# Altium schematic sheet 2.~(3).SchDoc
size 420 x 297 mm
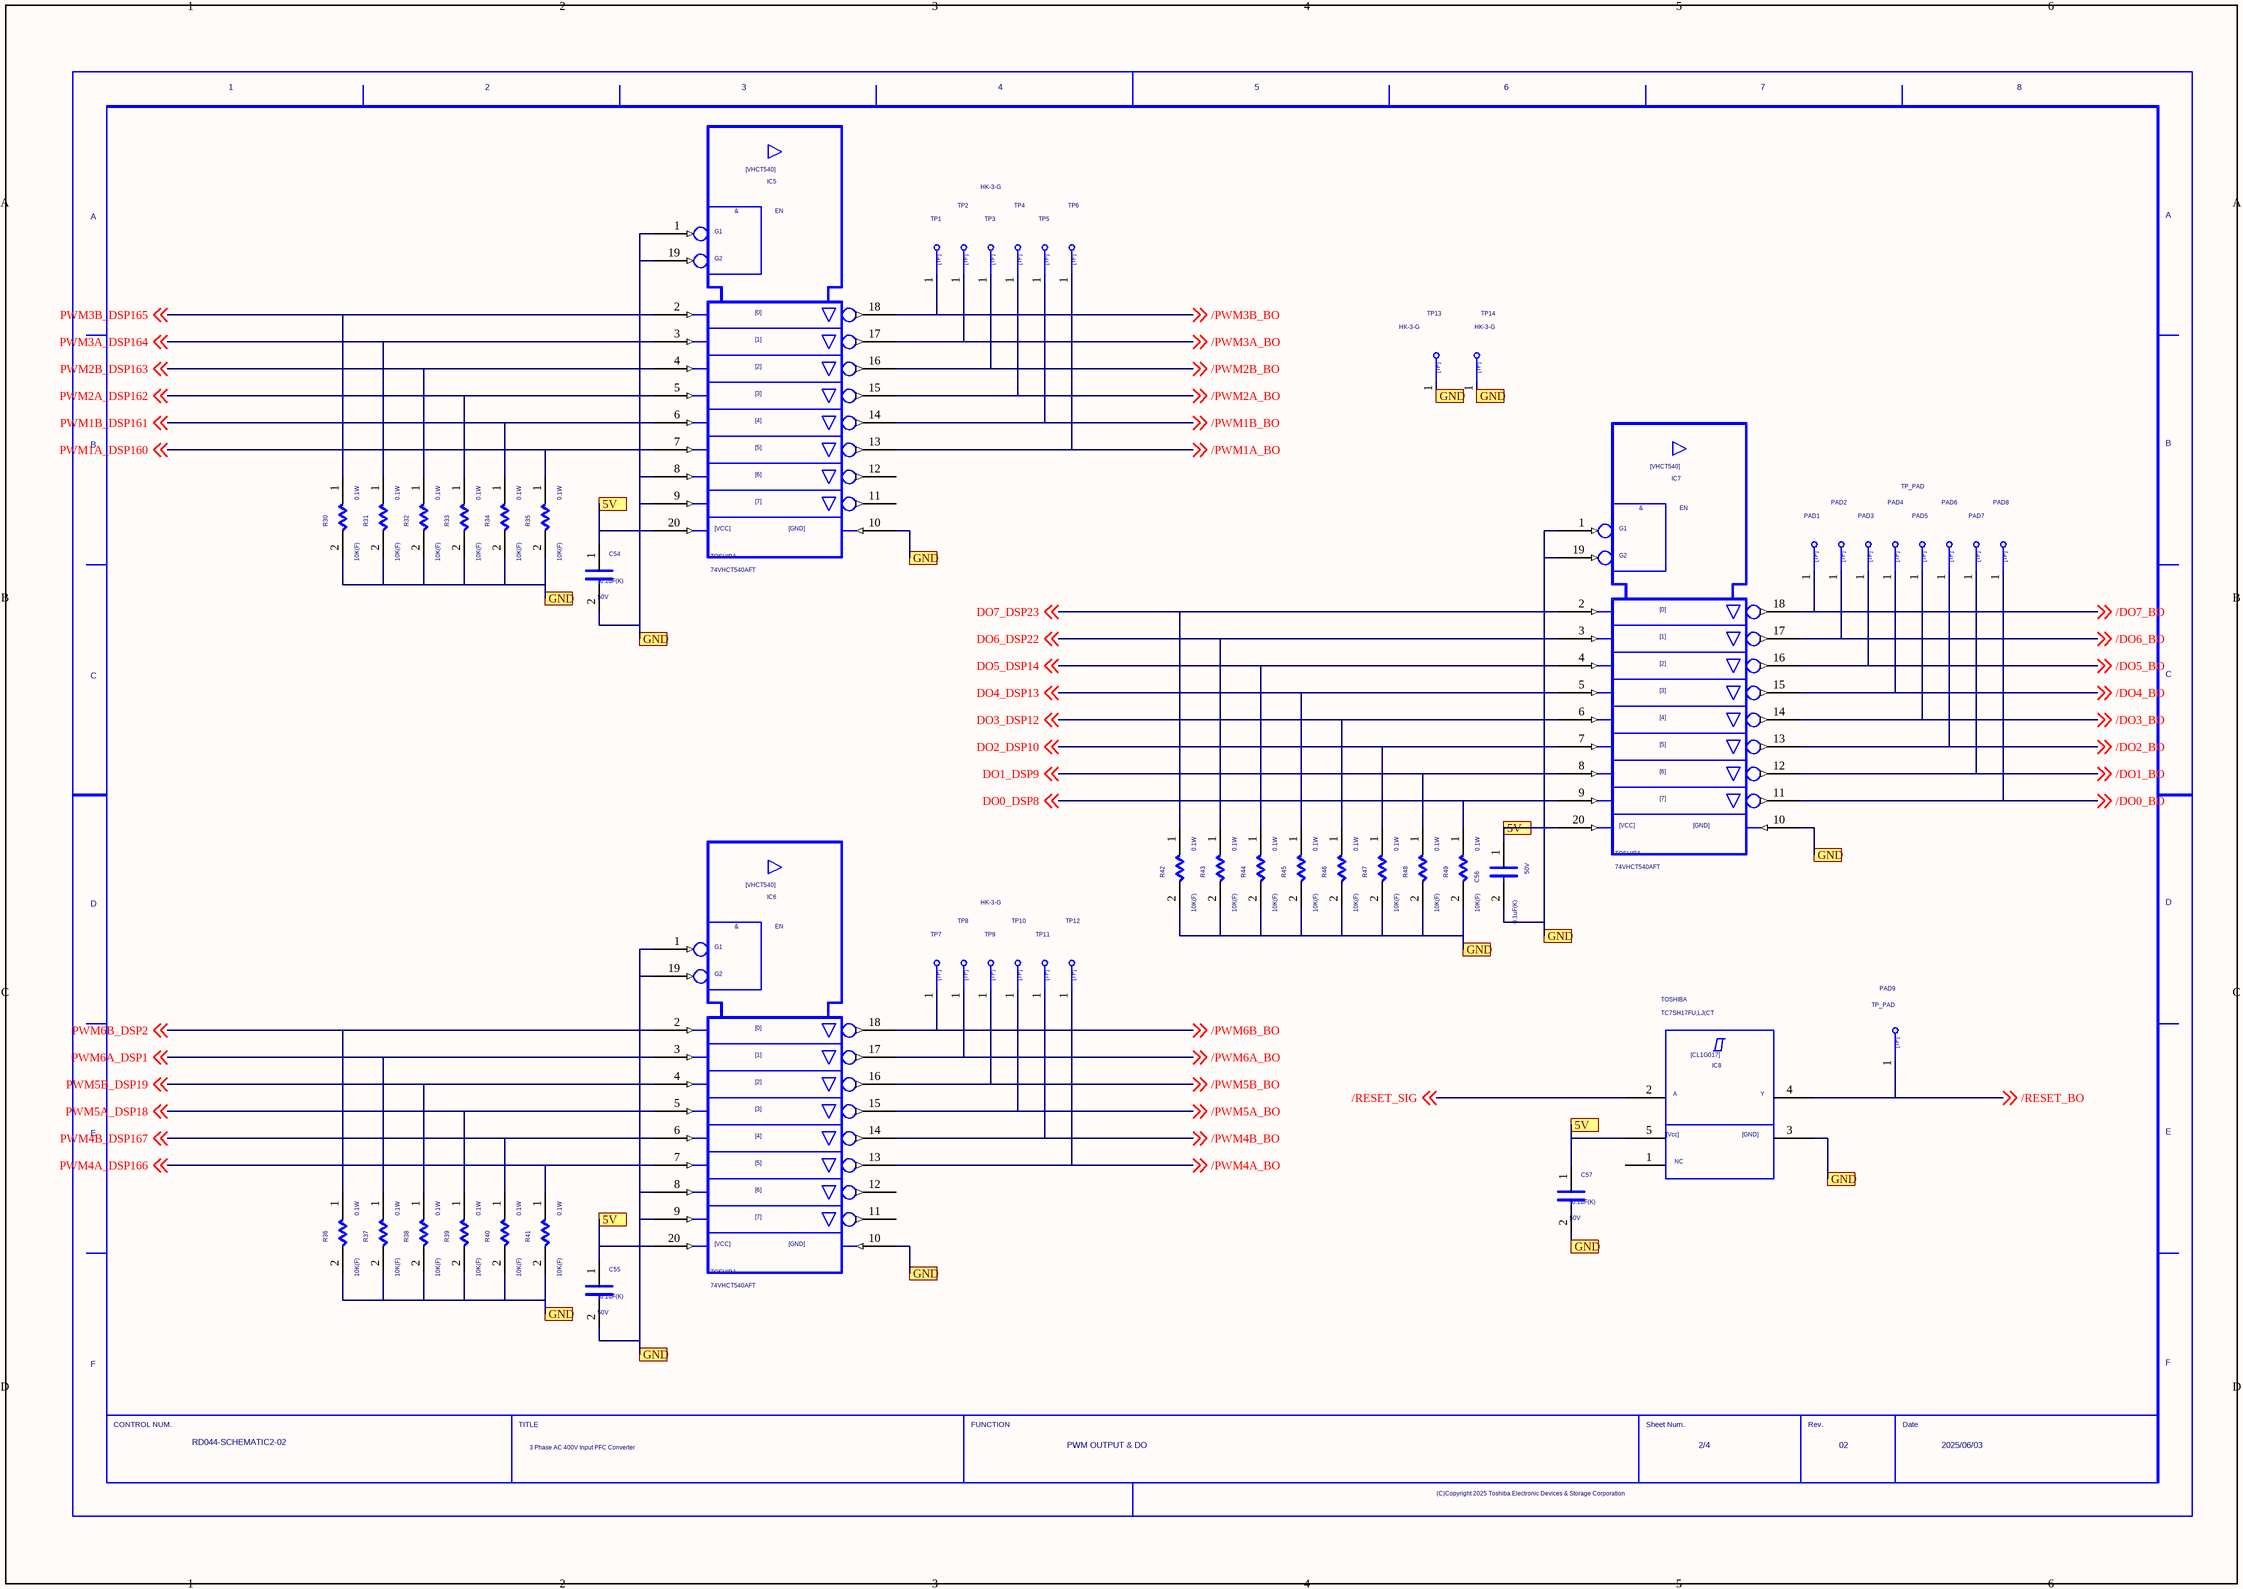
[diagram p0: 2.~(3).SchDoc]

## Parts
C54  VAL1: 0.1uF(K)  VAL2: 50V  (hidden comment: C)
C55  VAL1: 0.1uF(K)  VAL2: 50V  (hidden comment: C)
C56  VAL1: 0.1uF(K)  VAL2: 50V  (hidden comment: C)
C57  VAL1: 0.1uF(K)  VAL2: 50V  (hidden comment: C)
IC5  USERCOMPTEXT3: TOSHIBA  VAL3: 74VHCT540AFT  (hidden comment: VHC540)
IC6  USERCOMPTEXT3: TOSHIBA  VAL3: 74VHCT540AFT  (hidden comment: VHC540)
IC7  USERCOMPTEXT3: TOSHIBA  VAL3: 74VHCT540AFT  (hidden comment: VHC540)
IC8  USERCOMPTEXT3: TOSHIBA  VAL3: TC7SH17FU,LJ(CT  (hidden comment: CL1G017)
PAD1  TP  (value not drawn)
PAD2  VAL3: TP_PAD  (hidden comment: TP)
PAD3  TP  (value not drawn)
PAD4  TP  (value not drawn)
PAD5  TP  (value not drawn)
PAD6  TP  (value not drawn)
PAD7  TP  (value not drawn)
PAD8  TP  (value not drawn)
PAD9  VAL3: TP_PAD  (hidden comment: TP)
R30  VAL2: 0.1W  VAL1: 10K(F)  (hidden comment: R)
R31  VAL2: 0.1W  VAL1: 10K(F)  (hidden comment: R)
R32  VAL2: 0.1W  VAL1: 10K(F)  (hidden comment: R)
R33  VAL2: 0.1W  VAL1: 10K(F)  (hidden comment: R)
R34  VAL2: 0.1W  VAL1: 10K(F)  (hidden comment: R)
R35  VAL2: 0.1W  VAL1: 10K(F)  (hidden comment: R)
R36  VAL2: 0.1W  VAL1: 10K(F)  (hidden comment: R)
R37  VAL2: 0.1W  VAL1: 10K(F)  (hidden comment: R)
R38  VAL2: 0.1W  VAL1: 10K(F)  (hidden comment: R)
R39  VAL2: 0.1W  VAL1: 10K(F)  (hidden comment: R)
R40  VAL2: 0.1W  VAL1: 10K(F)  (hidden comment: R)
R41  VAL2: 0.1W  VAL1: 10K(F)  (hidden comment: R)
R42  VAL2: 0.1W  VAL1: 10K(F)  (hidden comment: R)
R43  VAL2: 0.1W  VAL1: 10K(F)  (hidden comment: R)
R44  VAL2: 0.1W  VAL1: 10K(F)  (hidden comment: R)
R45  VAL2: 0.1W  VAL1: 10K(F)  (hidden comment: R)
R46  VAL2: 0.1W  VAL1: 10K(F)  (hidden comment: R)
R47  VAL2: 0.1W  VAL1: 10K(F)  (hidden comment: R)
R48  VAL2: 0.1W  VAL1: 10K(F)  (hidden comment: R)
R49  VAL2: 0.1W  VAL1: 10K(F)  (hidden comment: R)
TP1  TP  (value not drawn)
TP2  VAL3: HK-3-G  (hidden comment: TP)
TP3  TP  (value not drawn)
TP4  TP  (value not drawn)
TP5  TP  (value not drawn)
TP6  TP  (value not drawn)
TP7  TP  (value not drawn)
TP8  VAL3: HK-3-G  (hidden comment: TP)
TP9  TP  (value not drawn)
TP10  TP  (value not drawn)
TP11  TP  (value not drawn)
TP12  TP  (value not drawn)
TP13  VAL3: HK-3-G  (hidden comment: TP)
TP14  VAL3: HK-3-G  (hidden comment: TP)
U?  DATE: 2025/06/03  DRAWINGNUMBER: RD044-SCHEMATIC2-02  TITLE: 3 Phase AC 400V Input PFC Converter  FUNCTION: PWM OUTPUT & DO  SHEETNUMBER: 2/4  REVISION: 02  (hidden comment: WAKU_DEF100_2018)

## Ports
5V, GND

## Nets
5V: C54.1 C55.1 C56.1 C57.1 IC5.20 IC6.20 IC7.20 IC8.5 ; port 5V
/DO0_BO: IC7.11 PAD8.1 ; off-sheet /DO0_BO
/DO1_BO: IC7.12 PAD7.1 ; off-sheet /DO1_BO
/DO2_BO: IC7.13 PAD6.1 ; off-sheet /DO2_BO
/DO3_BO: IC7.14 PAD5.1 ; off-sheet /DO3_BO
/DO4_BO: IC7.15 PAD4.1 ; off-sheet /DO4_BO
/DO5_BO: IC7.16 PAD3.1 ; off-sheet /DO5_BO
/DO6_BO: IC7.17 PAD2.1 ; off-sheet /DO6_BO
/DO7_BO: IC7.18 PAD1.1 ; off-sheet /DO7_BO
/PWM1A_BO: IC5.13 TP6.1 ; off-sheet /PWM1A_BO
/PWM1B_BO: IC5.14 TP5.1 ; off-sheet /PWM1B_BO
/PWM2A_BO: IC5.15 TP4.1 ; off-sheet /PWM2A_BO
/PWM2B_BO: IC5.16 TP3.1 ; off-sheet /PWM2B_BO
/PWM3A_BO: IC5.17 TP2.1 ; off-sheet /PWM3A_BO
/PWM3B_BO: IC5.18 TP1.1 ; off-sheet /PWM3B_BO
/PWM4A_BO: IC6.13 TP12.1 ; off-sheet /PWM4A_BO
/PWM4B_BO: IC6.14 TP11.1 ; off-sheet /PWM4B_BO
/PWM5A_BO: IC6.15 TP10.1 ; off-sheet /PWM5A_BO
/PWM5B_BO: IC6.16 TP9.1 ; off-sheet /PWM5B_BO
/PWM6A_BO: IC6.17 TP8.1 ; off-sheet /PWM6A_BO
/PWM6B_BO: IC6.18 TP7.1 ; off-sheet /PWM6B_BO
/RESET_BO: IC8.4 PAD9.1 ; off-sheet /RESET_BO
/RESET_SIG: IC8.2 ; off-sheet /RESET_SIG
DO0_DSP8: IC7.9 R49.1 ; off-sheet DO0_DSP8
DO1_DSP9: IC7.8 R48.1 ; off-sheet DO1_DSP9
DO2_DSP10: IC7.7 R47.1 ; off-sheet DO2_DSP10
DO3_DSP12: IC7.6 R46.1 ; off-sheet DO3_DSP12
DO4_DSP13: IC7.5 R45.1 ; off-sheet DO4_DSP13
DO5_DSP14: IC7.4 R44.1 ; off-sheet DO5_DSP14
DO6_DSP22: IC7.3 R43.1 ; off-sheet DO6_DSP22
DO7_DSP23: IC7.2 R42.1 ; off-sheet DO7_DSP23
GND: C54.2 C55.2 C56.2 C57.2 IC5.1 IC5.8 IC5.9 IC5.10 IC5.19 IC6.1 IC6.8 IC6.9 IC6.10 IC6.19 IC7.1 IC7.10 IC7.19 IC8.3 R30.2 R31.2 R32.2 R33.2 R34.2 R35.2 R36.2 R37.2 R38.2 R39.2 R40.2 R41.2 R42.2 R43.2 R44.2 R45.2 R46.2 R47.2 R48.2 R49.2 TP13.1 TP14.1 ; port GND
PWM1A_DSP160: IC5.7 R35.1 ; off-sheet PWM1A_DSP160
PWM1B_DSP161: IC5.6 R34.1 ; off-sheet PWM1B_DSP161
PWM2A_DSP162: IC5.5 R33.1 ; off-sheet PWM2A_DSP162
PWM2B_DSP163: IC5.4 R32.1 ; off-sheet PWM2B_DSP163
PWM3A_DSP164: IC5.3 R31.1 ; off-sheet PWM3A_DSP164
PWM3B_DSP165: IC5.2 R30.1 ; off-sheet PWM3B_DSP165
PWM4A_DSP166: IC6.7 R41.1 ; off-sheet PWM4A_DSP166
PWM4B_DSP167: IC6.6 R40.1 ; off-sheet PWM4B_DSP167
PWM5A_DSP18: IC6.5 R39.1 ; off-sheet PWM5A_DSP18
PWM5B_DSP19: IC6.4 R38.1 ; off-sheet PWM5B_DSP19
PWM6A_DSP1: IC6.3 R37.1 ; off-sheet PWM6A_DSP1
PWM6B_DSP2: IC6.2 R36.1 ; off-sheet PWM6B_DSP2

Not connected (* = marked no-connect by the designer): IC5 11 12; IC6 11 12; IC8 1

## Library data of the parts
C54-C57 = C: OriginalSymbolOrigin: (2540,7620); CDBNAME: C-GRM188R71H104KA93D; USERCOMPTEXT1: 1608
IC5-IC7 = VHC540: SAVEAREA0: -64373,-927,110287,89788; TIME: 09:37:32; UPDATEUSER: cae; SAVECOUNT: 1; OriginalSymbolOrigin: (7620,83820); CDBNAME: IC-74VHCT540AFT
IC8 = CL1G017: TIME: 16:09:43; UPDATEUSER: tomizawa-y; UPDATETIME: 12:13:51; SAVECOUNT: 12; SAVEAREA0: -8892,-376,44463,33313; OriginalSymbolOrigin: (7620,30480); MAXGCOUNT: 1; CDBNAME: IC-TC7SH17F; ADSCNVFLAG: ON
PAD1 PAD7 PAD8 = TP: TIME: 16:12:21; UPDATEUSER: fukuda-y; UPDATETIME: 16:18:11; SAVECOUNT: 2; SAVEAREA0: -242,-92,12810,7836; OriginalSymbolOrigin: (0,7620); CDBNAME: TP-PAD1.0; VAL3: TP_PAD
PAD2 PAD9 = TP: TIME: 16:12:21; UPDATEUSER: fukuda-y; UPDATETIME: 16:18:11; SAVECOUNT: 2; SAVEAREA0: -242,-92,12810,7836; OriginalSymbolOrigin: (0,7620); CDBNAME: TP-PAD1.0
PAD3-PAD6 = TP: TIME: 16:12:21; UPDATEUSER: fukuda-y; UPDATETIME: 16:18:11; SAVECOUNT: 2; SAVEAREA0: -242,-92,12810,7836; OriginalSymbolOrigin: (0,7620); CDBNAME: TP-PAD1.0; VAL3: HK-3-G
R30-R49 = R: OriginalSymbolOrigin: (5080,5080); CDBNAME: R-ERJ3EKF1002V; USERCOMPTEXT1: 1608
TP1 TP3-TP7 TP9-TP12 = TP: TIME: 16:12:21; UPDATEUSER: fukuda-y; UPDATETIME: 16:18:11; SAVECOUNT: 2; SAVEAREA0: -242,-92,12810,7836; OriginalSymbolOrigin: (0,7620); CDBNAME: TP-HK-3-G; VAL3: HK-3-G
TP2 TP8 TP13 TP14 = TP: TIME: 16:12:21; UPDATEUSER: fukuda-y; UPDATETIME: 16:18:11; SAVECOUNT: 2; SAVEAREA0: -242,-92,12810,7836; OriginalSymbolOrigin: (0,7620); CDBNAME: TP-HK-3-G
U? = WAKU_DEF100_2018: PLOTTIME: HH:MM; SAVEAREA0: -45080,-4508,463680,304612; TIME: 13:54:34; UPDATEUSER: e5025010; UPDATETIME: 15:56:23; SAVECOUNT: 4; OriginalSymbolOrigin: (10160,284480)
